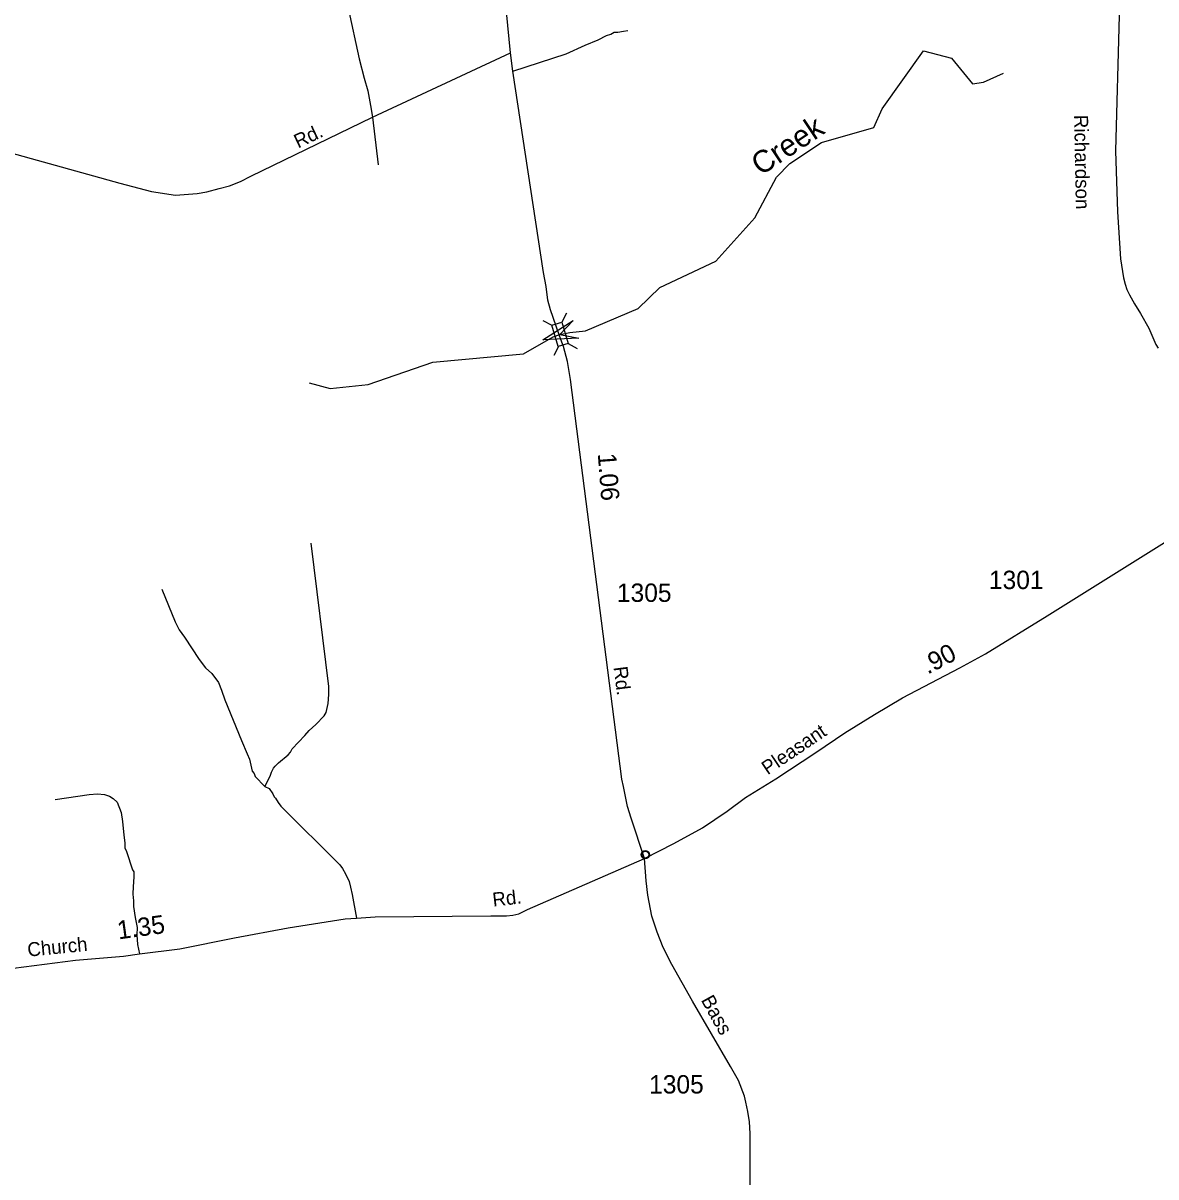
# Model space of a CAD drawing. Extents: x 2220236 to 2384410, y 720751 to 894131.
# Drawn here: x 2268370 to 2276076, y 812295 to 820140 of the extents above; entities that cross this region are included whole.
import ezdxf

# ---------------------------------------------------------------- set-up
doc = ezdxf.new("R2010")
doc.units = 0
doc.layers.add('Default', color=7, linetype='Continuous')

msp = doc.modelspace()

# ---------------------------------------------------------------- linework, layer by layer
at = {"layer": 'Default'}
for p, q in [((2270747.9, 819500.1), (2270784.5, 819176.6)), ((2272067.2, 818166.3), (2272034.6, 818105.5)), ((2271906.2, 818117.7), (2271967, 818085.1)), ((2272011.9, 817940.8), (2271979.3, 817880)), ((2272078, 817960.8), (2272138.8, 817928.2))]:
    msp.add_line(p, q, dxfattribs=at)
for points in [[(2275687.5, 820388.2), (2275742.9, 820375.2), (2275778.8, 820349.1), (2275800.7, 820319.9), (2275810.8, 820295.9), (2275826.9, 820191.6), (2275800.1, 819271.5), (2275813.9, 818855.9), (2275835.1, 818536.2), (2275856.2, 818406.6), (2275866.6, 818364.6), (2275879, 818328.7), (2275895.3, 818292.8), (2275930.2, 818230.8), (2275971.5, 818165.8), (2276027.6, 818065.4), (2276074.4, 817954.8), (2276091, 817929.6)], [(2270581.2, 820240.6), (2270657, 819896.9), (2270689.8, 819765.5), (2270715.1, 819679.6), (2270732.7, 819578.5), (2270747.9, 819500.1)], [(2271686.2, 819937.3), (2271658.4, 820215.3)], [(2271701.1, 819812.7), (2272063.8, 819930.2), (2272193.2, 819989.3), (2272282.8, 820026.2), (2272338.5, 820054.6), (2272368.5, 820065), (2272390.4, 820077.2), (2272416.4, 820077.4), (2272454.1, 820085.6), (2272484.2, 820090)], [(2268024, 819330.8), (2269029.2, 819050.3), (2269243.9, 818994.7), (2269406.8, 818969.4), (2269554.6, 818982), (2269620.2, 818992.2), (2269703.6, 819014.9), (2269774.3, 819032.6), (2269849.2, 819061.8), (2269918.7, 819098.4), (2270747.9, 819500.1), (2271686.2, 819937.3)], [(2270317.1, 817694.8), (2270459.2, 817655.8), (2270717.1, 817683.3), (2271157.2, 817834.9), (2271773.2, 817891), (2271976, 818007.4), (2272022.2, 818022), (2272088.9, 818036.5), (2272196.2, 818046.2), (2272553.2, 818199.6), (2272701.2, 818340.9), (2273083, 818519.9), (2273347.2, 818816.2), (2273494.2, 819092), (2273585.2, 819185.2), (2273800.1, 819328.3), (2274157.1, 819429.2), (2274214.1, 819555.9), (2274494.2, 819950.3), (2274686.1, 819900.4), (2274829.1, 819726.9), (2274904.1, 819738.4), (2275039.7, 819799)], [(2272016.9, 818020.7), (2271958.3, 818189.8), (2271939.7, 818255.8), (2271928.8, 818347.6), (2271909.9, 818443.4), (2271701.1, 819812.7), (2271686.2, 819937.3)], [(2272596.2, 814458.7), (2272506.5, 814734.7), (2272481.7, 814812.4), (2272454.5, 814950.1), (2272442, 815000), (2272094.7, 817717.4), (2272073.4, 817839.2), (2272046.5, 817940.9), (2272028.1, 817988.7), (2272016.9, 818020.7)], [(2272596.2, 814458.7), (2272796.3, 814560.7), (2272990.7, 814669.2), (2273160.5, 814781.6), (2273284.7, 814874), (2273490.8, 815001.6), (2273762.6, 815181), (2273960.7, 815313.2), (2274160.8, 815439.7), (2274352, 815551.7), (2274741.9, 815755.2), (2274916.7, 815850.8), (2275336.1, 816110.6), (2276425.3, 816790.5), (2276681.8, 816929)], [(2270015.7, 814949.2), (2270050.9, 815019.4), (2270060.7, 815047.6), (2270074.4, 815073.7), (2270084.3, 815087.7), (2270108.2, 815110), (2270173.5, 815164.6), (2270189.5, 815182.7), (2270201.1, 815204.9), (2270286.2, 815295.5), (2270315.9, 815329.8), (2270361.5, 815370.3), (2270418.9, 815428.7), (2270430.8, 815452.8), (2270446.2, 815512.9), (2270449.5, 815575), (2270449, 815629), (2270330, 816603.4)], [(2269313.4, 816289.9), (2269405.4, 816068.9), (2269431.9, 816015.1), (2269468.3, 815965.6), (2269567.7, 815812.6), (2269610.3, 815754.9), (2269654.7, 815717.4), (2269699.2, 815655.9), (2269719.7, 815604.1), (2269742.2, 815538.2), (2269854.8, 815261.6), (2269895.5, 815172), (2269909.9, 815134.1), (2269928.7, 815054.3), (2269940.9, 815036.5), (2269949.1, 815016.5), (2270015.7, 814949.2)], [(2270015.7, 814949.2), (2270043.8, 814935.4), (2270068.1, 814899.7), (2270078.2, 814879.9), (2270086.4, 814869.9), (2270104.6, 814840.2), (2270122.9, 814816.2), (2270524.5, 814416.2), (2270542.6, 814392.4), (2270562.9, 814356.6), (2270587.6, 814302.9), (2270597.8, 814264.9), (2270608.3, 814215.1), (2270637.8, 814053.4)], [(2268589.1, 814861.9), (2268820.8, 814895.9), (2268876.6, 814900.5), (2268924.7, 814894.9), (2268956.9, 814883.3), (2268982.9, 814867.5), (2269011.2, 814841.8), (2269037.7, 814772), (2269046.5, 814710.3), (2269055.2, 814618.3), (2269061.7, 814566.4), (2269062, 814532.4), (2269074.2, 814506.6), (2269115.5, 814382.9), (2269123.6, 814369), (2269123.9, 814337), (2269122.1, 814299), (2269118.5, 814269.1), (2269117, 814217.2), (2269121.5, 814171.1), (2269121.7, 814133.1), (2269132.4, 814059.3), (2269145.2, 813991.4), (2269143.5, 813941.5), (2269148.2, 813875.6), (2269162.8, 813811.7)], [(2267951.6, 813669.3), (2268727.3, 813767.5), (2269053, 813796.6), (2269162.8, 813811.7), (2269436.3, 813846.3), (2269808.7, 813920.4), (2270173, 813988.4), (2270561.9, 814048.7), (2270637.8, 814053.4), (2270765.7, 814062.7), (2271551.2, 814070.1), (2271659.2, 814069), (2271701.1, 814073.4), (2271742.9, 814083.9), (2271800.6, 814112.3), (2272596.2, 814458.7)], [(2273317.2, 811574), (2273315.3, 812589.1), (2273311.5, 812670.3), (2273300.2, 812740.2), (2273287, 812802.5), (2273277.5, 812844), (2273237, 812950.4), (2273181.9, 813045.9), (2272922.7, 813490.8), (2272783.1, 813739.2), (2272724.6, 813854.4), (2272683, 813958.2), (2272647.2, 814067.8), (2272620.8, 814209.4), (2272609.4, 814307.6), (2272596.2, 814458.7)]]:
    msp.add_lwpolyline(points, dxfattribs=at)
for points in [[(2272149.6, 817996.3), (2271906, 817984.9), (2272111.2, 818116.6), (2272022.2, 818022)], [(2272034.6, 818105.5), (2272078.3, 817960.9), (2272010.7, 817940.5), (2271967, 818085.1)], [(2272579, 814489.6), (2272579.3, 814491.3), (2272579.8, 814493.3), (2272580.7, 814495.5), (2272581.6, 814497.2), (2272582.6, 814499), (2272583.8, 814500.5), (2272585, 814501.9), (2272586.4, 814503.3), (2272588.1, 814504.7), (2272589.7, 814505.8), (2272591.2, 814506.6), (2272592.8, 814507.4), (2272594.4, 814508.1), (2272596.1, 814508.6), (2272597.5, 814509), (2272598.9, 814509.2), (2272600.2, 814509.4), (2272602.1, 814509.5), (2272603.5, 814509.5), (2272605.2, 814509.4), (2272606.7, 814509.2), (2272608.2, 814508.9), (2272609.7, 814508.5), (2272611.3, 814507.9), (2272613.3, 814507), (2272615.2, 814505.9), (2272616.8, 814504.8), (2272618.4, 814503.6), (2272619.4, 814502.6), (2272620.6, 814501.3), (2272621.8, 814499.9), (2272622.7, 814498.5), (2272623.7, 814497), (2272624.4, 814495.4), (2272625.1, 814493.9), (2272625.5, 814492.3), (2272625.9, 814490.9), (2272626.3, 814489.1), (2272626.5, 814487.7), (2272626.5, 814485.8), (2272626.5, 814484.1), (2272626.3, 814482.3), (2272626, 814480.7), (2272625.5, 814478.8), (2272624.9, 814477), (2272624.2, 814475.5), (2272623.3, 814473.6), (2272622.3, 814472), (2272621.2, 814470.6), (2272619.9, 814469.1), (2272618.3, 814467.6), (2272616.8, 814466.4), (2272615.3, 814465.3), (2272614, 814464.5), (2272611.9, 814463.6), (2272609.7, 814462.7), (2272607.9, 814462.3), (2272605.9, 814461.9), (2272604.5, 814461.7), (2272603.2, 814461.7), (2272601.5, 814461.7), (2272600.2, 814461.8), (2272598.4, 814462), (2272596.6, 814462.4), (2272595.2, 814462.8), (2272593.7, 814463.4), (2272592.3, 814464), (2272591.1, 814464.7), (2272589, 814465.9), (2272587.3, 814467.2), (2272585.8, 814468.6), (2272584.4, 814470.1), (2272583.5, 814471.3), (2272582.6, 814472.5), (2272581.3, 814474.7), (2272580.8, 814475.8), (2272580.3, 814477), (2272579.5, 814479.5), (2272579, 814481.7), (2272578.8, 814483.2), (2272578.7, 814485.2), (2272578.7, 814486.6), (2272578.8, 814488.6)], [(2272579, 814489.6), (2272579.3, 814491.3), (2272579.8, 814493.3), (2272580.7, 814495.5), (2272581.6, 814497.2), (2272582.6, 814499), (2272583.8, 814500.5), (2272585, 814501.9), (2272586.4, 814503.3), (2272588.1, 814504.7), (2272589.7, 814505.8), (2272591.2, 814506.6), (2272592.8, 814507.4), (2272594.4, 814508.1), (2272596.1, 814508.6), (2272597.5, 814509), (2272598.9, 814509.2), (2272600.2, 814509.4), (2272602.1, 814509.5), (2272603.5, 814509.5), (2272605.2, 814509.4), (2272606.7, 814509.2), (2272608.2, 814508.9), (2272609.7, 814508.5), (2272611.3, 814507.9), (2272613.3, 814507), (2272615.2, 814505.9), (2272616.8, 814504.8), (2272618.4, 814503.6), (2272619.4, 814502.6), (2272620.6, 814501.3), (2272621.8, 814499.9), (2272622.7, 814498.5), (2272623.7, 814497), (2272624.4, 814495.4), (2272625.1, 814493.9), (2272625.5, 814492.3), (2272625.9, 814490.9), (2272626.3, 814489.1), (2272626.5, 814487.7), (2272626.5, 814485.8), (2272626.5, 814484.1), (2272626.3, 814482.3), (2272626, 814480.7), (2272625.5, 814478.8), (2272624.9, 814477), (2272624.2, 814475.5), (2272623.3, 814473.6), (2272622.3, 814472), (2272621.2, 814470.6), (2272619.9, 814469.1), (2272618.3, 814467.6), (2272616.8, 814466.4), (2272615.3, 814465.3), (2272614, 814464.5), (2272611.9, 814463.6), (2272609.7, 814462.7), (2272607.9, 814462.3), (2272605.9, 814461.9), (2272604.5, 814461.7), (2272603.2, 814461.7), (2272601.5, 814461.7), (2272600.2, 814461.8), (2272598.4, 814462), (2272596.6, 814462.4), (2272595.2, 814462.8), (2272593.7, 814463.4), (2272592.3, 814464), (2272591.1, 814464.7), (2272589, 814465.9), (2272587.3, 814467.2), (2272585.8, 814468.6), (2272584.4, 814470.1), (2272583.5, 814471.3), (2272582.6, 814472.5), (2272581.3, 814474.7), (2272580.8, 814475.8), (2272580.3, 814477), (2272579.5, 814479.5), (2272579, 814481.7), (2272578.8, 814483.2), (2272578.7, 814485.2), (2272578.7, 814486.6), (2272578.8, 814488.6)]]:
    msp.add_lwpolyline(points, close=True, dxfattribs=at)
for centre, radius in [((2272602.7, 814485.8), 28.8), ((2272602.7, 814485.8), 28.8), ((2272602.6, 814485.9), 23.4), ((2272602.6, 814485.9), 23.4)]:
    msp.add_circle(centre, radius, dxfattribs=at)

# ---------------------------------------------------------------- texts
for s, height, rotation, p in [('Creek', 150, 33.66503, (2273387.5, 819098.2)), ('Richardson', 95, 271.0871, (2275519.4, 819514.8)), ('Rd.', 95, 25.28224, (2270240.7, 819286.8)), ('1.06', 125, 274.35729, (2272279, 817211.8)), ('.90', 125, 27.56133, (2274523.9, 815709.4)), ('Rd.', 95, 277.28326, (2272386.1, 815760.5)), ('Pleasant', 95, 34.04977, (2273434.5, 815024.8)), ('Rd.', 95, 6.61296, (2271568.4, 814132)), ('1.35', 125, 7.83124, (2269019.2, 813909.4)), ('Church', 95, 5.577, (2268404.2, 813792.1)), ('Bass', 95, 298.93223, (2272979.1, 813497.5))]:
    msp.add_text(s, height=height, rotation=rotation, dxfattribs=at).set_placement(p)
for s, p in [('1301', (2274939.8, 816291.4)), ('1305', (2272409.2, 816204.3)), ('1305', (2272628.4, 812861.9))]:
    msp.add_text(s, height=125, dxfattribs=at).set_placement(p)

doc.saveas('drawing.dxf')
